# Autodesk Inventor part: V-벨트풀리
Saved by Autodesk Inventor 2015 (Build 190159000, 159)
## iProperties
Created: 2025-08
Part Number: V-벨트풀리
Material: 일반
Document SubType Name: Modeling
Designer: USER
Density: 1 g/cm^3
Appearance: 기본값
Author: USER
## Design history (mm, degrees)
node "V-벨트풀리1"
node "솔리드1"
node "기준1"
